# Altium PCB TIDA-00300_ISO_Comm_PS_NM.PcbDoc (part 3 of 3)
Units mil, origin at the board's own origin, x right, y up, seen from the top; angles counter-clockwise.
Board outline 2559.06 x 6299.21 mil, 4 copper layers (Top Layer, GND Layer, PWR Layer, Bottom Layer), stack 61.6 mil thick; 303 components, 144 nets, 678 pads, 244 vias.
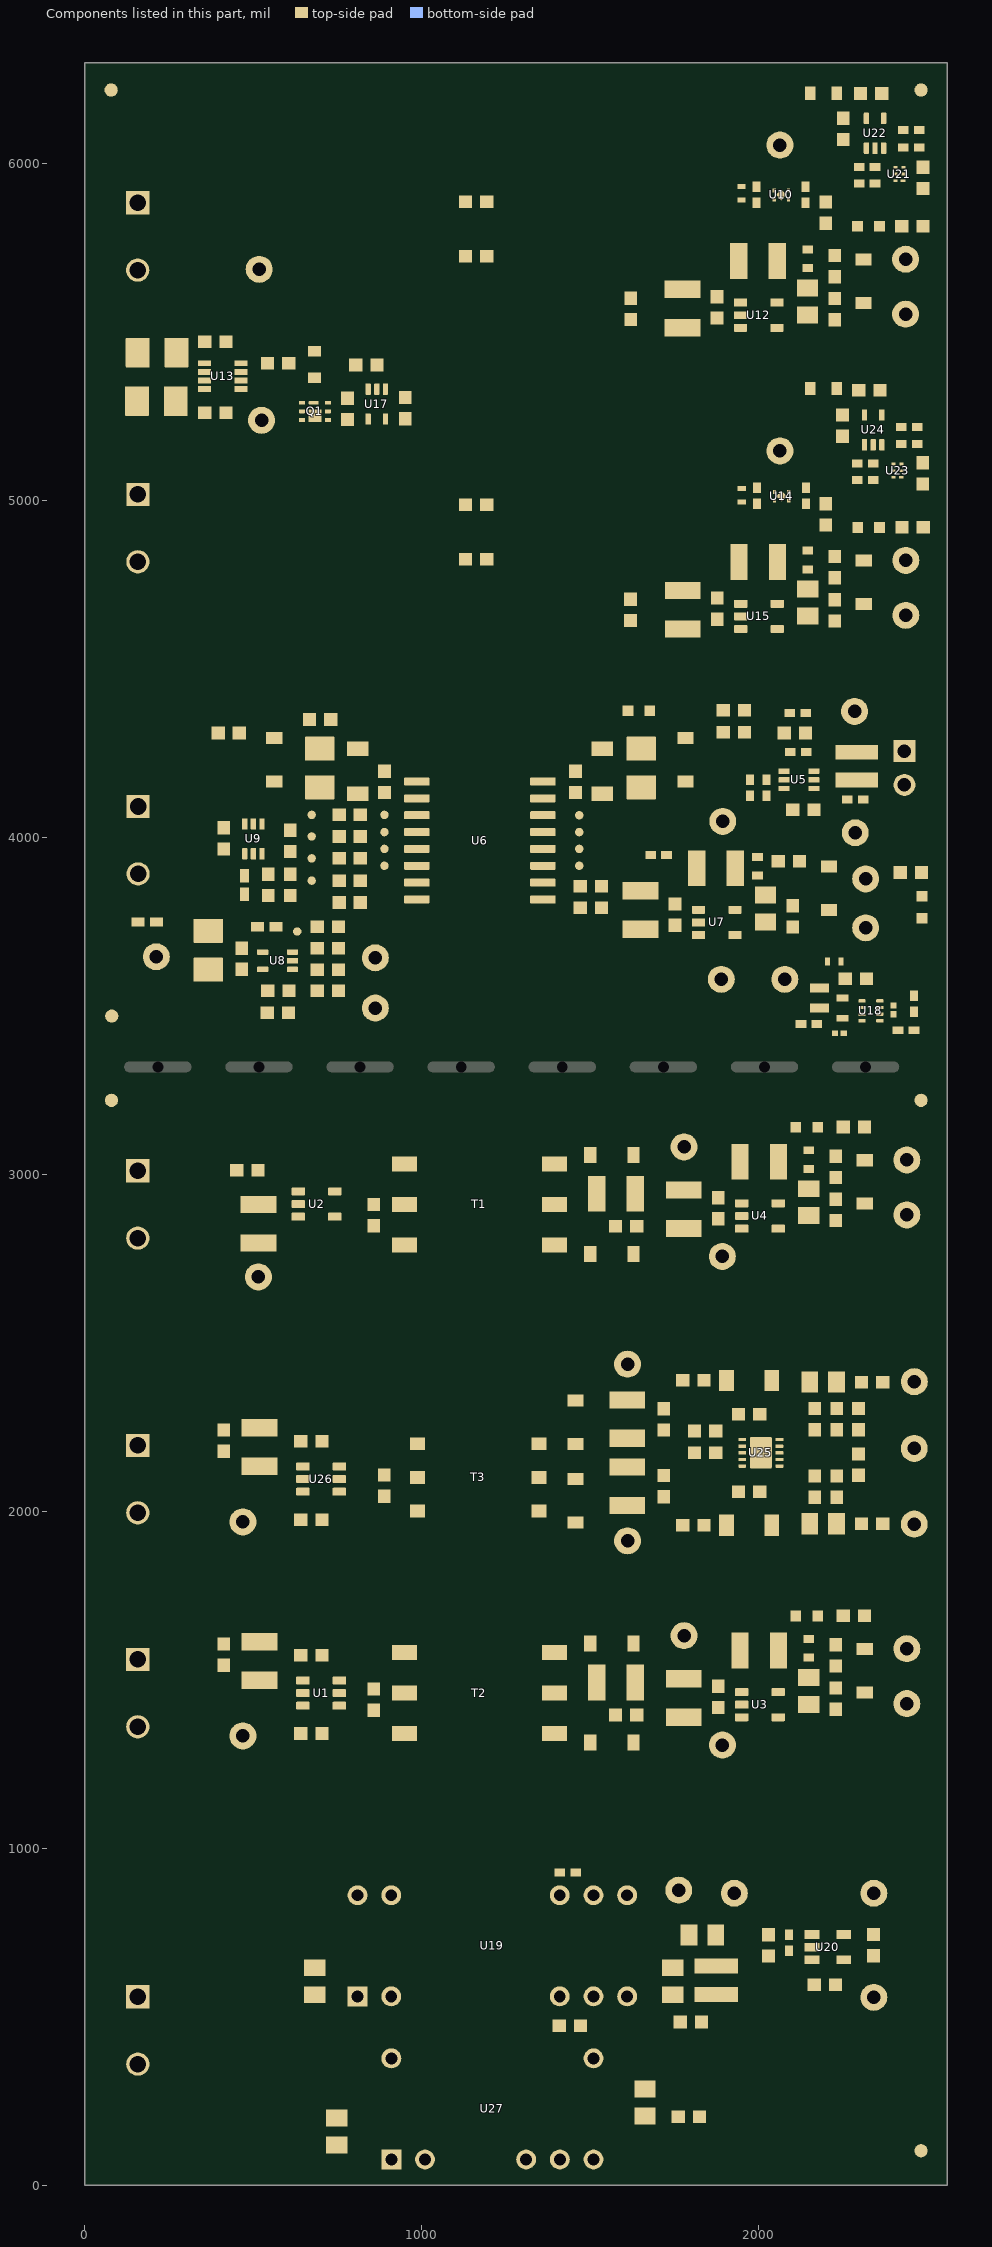
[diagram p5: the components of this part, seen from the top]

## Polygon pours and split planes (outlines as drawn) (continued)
NetC64_2 on Top Layer "vdd" (solid, remove dead copper, pour order 238): 1962.14,4669.8 1560.87,4669.8 1550.07,4659 1550.07,4561.8 1562.07,4549.8 1895.34,4549.8 1903.34,4557.8 1903.34,4634.58 1911.07,4642.31 1963.5,4642.31 1968.55,4647.36 1968.55,4663.11
IGND_5 on Top Layer "vdd" (solid, remove dead copper, pour order 236): 1860.07,4871.8 1852.07,4863.8 1852.07,4775.8 1845.07,4768.8 1670.07,4768.8 1661.07,4759.8 1661.07,4693.8 1665.07,4689.8 1915.07,4689.8 1922.07,4682.8 1964.55,4682.8 1968.55,4686.8 1968.55,4869.33 1966.07,4871.8
NetC68_2 on Top Layer "vdd" (solid, remove dead copper, pour order 234): 2165.07,4879.8 2168.07,4876.8 2168.07,4839.8 2163.07,4834.8 2100.07,4834.8 2089.07,4823.8 2089.07,4767.8 2082.07,4760.8 2042.07,4760.8 2027.07,4775.8 2027.07,4874.73 2032.14,4879.8
NetC66_2 on Top Layer "vdd" (solid, remove dead copper, pour order 232): 2163.79,4809.09 2111.79,4809.09 2107.79,4805.09 2107.79,4711.09 2110.79,4708.09 2193.79,4708.09 2201.79,4700.09 2201.79,4688.09 2205.79,4684.09 2248.79,4684.09 2251.79,4687.09 2251.79,4786.09 2248.79,4789.09 2183.79,4789.09
IGND_5 on Top Layer "vdd" (solid, remove dead copper, pour order 228): 2479.79,4723.09 2494.79,4708.09 2494.79,4574.09 2473.79,4553.09 2115.79,4553.09 2104.79,4564.09 2104.79,4680.09 2110.79,4686.09 2175.79,4686.09 2198.78,4663.11 2269.01,4663.11 2274.79,4668.89 2274.79,4716.09 2281.79,4723.09
IGND_4 on Top Layer "vdd" (solid, remove dead copper, pour order 226): 2479.14,5616.78 2494.14,5601.78 2494.14,5467.78 2480.21,5453.85 2108.07,5453.85 2104.14,5457.78 2104.14,5573.78 2110.14,5579.78 2175.14,5579.78 2198.12,5556.8 2268.36,5556.8 2274.14,5562.58 2274.14,5609.78 2281.14,5616.78
+5.0V_3.3V_VDC_4 on Top Layer "vdd" (solid, remove dead copper, pour order 224): 27 vertices, not listed, extent 2169.46,5675.49 2517.93,5955.85
NetC49_2 on Top Layer "vdd" (solid, remove dead copper, pour order 222): 2163.14,5702.78 2111.14,5702.78 2107.14,5698.78 2107.14,5604.78 2110.14,5601.78 2193.14,5601.78 2201.14,5593.78 2201.14,5581.78 2205.14,5577.78 2248.14,5577.78 2251.14,5580.78 2251.14,5679.78 2248.14,5682.78 2183.14,5682.78
NetC51_2 on Top Layer "vdd" (solid, remove dead copper, pour order 220): 2164.42,5773.49 2167.42,5770.49 2167.42,5733.49 2162.42,5728.49 2099.42,5728.49 2088.42,5717.49 2088.42,5661.49 2081.42,5654.49 2041.42,5654.49 2026.42,5669.49 2026.42,5768.42 2031.49,5773.49
IGND_4 on Top Layer "vdd" (solid, remove dead copper, pour order 218): 1859.42,5765.49 1851.42,5757.49 1851.42,5669.49 1844.42,5662.49 1669.42,5662.49 1660.42,5653.49 1660.42,5587.49 1664.42,5583.49 1914.42,5583.49 1921.42,5576.49 1963.89,5576.49 1967.89,5580.49 1967.89,5763.02 1965.42,5765.49
NetC47_2 on Top Layer "vdd" (solid, remove dead copper, pour order 216): 1961.49,5563.49 1560.22,5563.49 1549.42,5552.69 1549.42,5466.09 1561.65,5453.85 1897,5453.85 1902.69,5459.54 1902.69,5528.27 1910.42,5536 1962.84,5536 1967.89,5541.05 1967.89,5556.8
NetC56_1 on Top Layer "vdd" (solid, remove dead copper, pour order 214): 1942.58,5019.29 1929.16,5032.72 1929.16,5058.89 1934.07,5063.8 2010.07,5063.8 2014.07,5059.8 2014.07,5022.29 2011.07,5019.29
DVDD_I_5 on Top Layer "vdd" (solid, remove dead copper, pour order 212): 1873.02,5008.8 1862.45,4998.24 1862.45,4896.41 1866.06,4892.8 1952.07,4892.8 1962.07,4902.8 1962.07,5006.8 1960.07,5008.8
NetC39_1 on Top Layer "vdd" (solid, remove dead copper, pour order 206): 1941.93,5912.98 1928.5,5926.41 1928.5,5952.58 1933.42,5957.49 2009.42,5957.49 2013.42,5953.49 2013.42,5915.98 2010.42,5912.98
DVDD_I_4 on Top Layer "vdd" (solid, remove dead copper, pour order 200): 1861.42,5902.49 1856.42,5897.49 1856.42,5791.49 1861.42,5786.49 1951.42,5786.49 1961.42,5796.49 1961.42,5900.49 1959.42,5902.49
NetD22_1 on Top Layer "vdd" (solid, remove dead copper, pour order 192): 623,5271.8 619,5267.8 619,5208.87 622.07,5205.8 730.02,5205.8 735,5210.78 735,5268.8 732,5271.8
GND_4 on Top Layer "vdd" (solid, remove dead copper, pour order 180): 199,5252.54 182,5235.54 80.73,5235.54 68,5248.28 68,5487.65 78,5497.65 194.15,5497.65 199,5492.8
no net on Top Layer "vdd" (solid, remove dead copper, pour order 178): 158,5457.8
VCC_LS_5 on Top Layer "vdd" (solid, remove dead copper, pour order 176): 550.89,4933 455,5028.89 455,5300.8 439,5316.8 439,5338.8 441,5340.8 561,5340.8 566,5335.8 566,5141 664,5043 1141.34,5043 1150.72,5033.62 1150.72,4939.72 1144,4933
DVDD_5 on Top Layer "vdd" (solid, remove dead copper, pour order 174): 119,4979.85 123,4975.85 189,4975.85 378,5164.85 378,5361.8 376,5363.8 250,5363.8 233,5346.8 233,5230.8 119,5116.8
DVDD_4 on Top Layer "vdd" (solid, remove dead copper, pour order 172): 351.98,5601.87 228,5725.85 125,5725.85 117,5717.85 117,5552.8 127,5542.8 208,5542.8 234,5516.8 234,5390.8 241,5383.8 319,5383.8 332,5370.8 372,5370.8 376,5374.8 376,5577.85
VCC_LS_4 on Top Layer "vdd" (solid, remove dead copper, pour order 170): 18 vertices, not listed, extent 441,5374.8 1150.46,5792
GND_2 on Top Layer "vdd" (solid, remove dead copper, pour order 164): 125.64,2849.8 578.89,2849.8 613.74,2814.94 613.74,2671.8 595.74,2653.8 117.74,2653.8 117.74,2841.9
NetC1_2 on Top Layer "vdd" (solid, remove dead copper, pour order 162): 486.74,2975.8 454.74,2943.8 454.74,2886.8 459.74,2881.8 573.74,2881.8 585.74,2893.8 585.74,3052.8 578.74,3059.8 493.6,3059.8 486.74,3052.94
IGND_3 on Top Layer "vdd" (solid, remove dead copper, pour order 140): 2319.66,3509.85 2324.71,3514.91 2324.71,3539.01 2328.77,3543.06 2372.98,3543.06 2377.77,3547.85 2377.77,3605.85 2371.77,3611.85 2302.58,3611.85 2297.58,3606.85 2297.58,3552.89 2281.37,3536.68 2228.66,3536.68 2228.66,3509.85
NetC70_1 on Top Layer "vdd" (solid, remove dead copper, pour order 138): 2228.92,3647.85 2228.66,3604.74 2218.77,3594.85 2125.77,3594.85 2100.77,3619.85 2019.77,3619.85 2011.53,3611.62 2011.53,3546.08 2020.77,3536.85 2202.77,3536.85 2224.77,3558.85 2271.77,3558.85 2275.77,3562.85 2275.77,3645.07 2272.98,3647.85
NetC35_2 on Top Layer "vdd" (solid, remove dead copper, pour order 136): 2004.08,3972.05 2012.77,3963.37 2012.77,3929.55 2009.27,3926.05 1965.49,3926.05 1957.49,3918.05 1957.49,3772.05 1954.49,3769.05 1906.24,3769.05 1901.49,3773.8 1901.49,3965.05 1908.49,3972.05
+5.0V_VDC_3 on Top Layer "vdd" (solid, remove dead copper, pour order 134): 19 vertices, not listed, extent 1982.77,3776.85 2362.77,3951.85
IGND_3 on Top Layer "vdd" (solid, remove dead copper, pour order 130): 2370.49,3787.13 2370.49,3680.57 2361.77,3671.85 1988.77,3671.85 1980.49,3680.13 1980.49,3773.05 1986.49,3779.05 2051.49,3779.05 2074.47,3756.07 2171.98,3756.07 2177.82,3761.91 2177.82,3795.91 2182.97,3801.05 2356.57,3801.05
NetC31_2 on Top Layer "vdd" (solid, remove dead copper, pour order 128): 1700.49,3967.1 1695.54,3972.05 1590.97,3972.05 1581.77,3962.85 1581.77,3791.35 1590.77,3782.35 1791.19,3782.35 1798.49,3775.05 1842.49,3775.05 1842.49,3824.05 1837.49,3829.05 1734.49,3829.05 1700.49,3863.05
IGND_3 on Top Layer "vdd" (solid, remove dead copper, pour order 124): 17 vertices, not listed, extent 1574.49,3592.05 1843.24,3763.05
DVDD_I_5.4V_3 on Top Layer "vdd" (solid, remove dead copper, pour order 114): 2141.8,4149.67 2141.8,3991.82 2160.77,3972.85 2335.84,3972.85 2351.84,3988.85 2351.84,4064.8 2343.79,4072.85 2217.77,4072.85 2192.77,4097.85 2192.77,4145.37 2184.29,4153.85 2145.98,4153.85
NetC25_1 on Top Layer "vdd" (solid, remove dead copper, pour order 108): 2124.77,4232.85 2134.77,4222.85 2470.77,4222.85 2482.77,4234.85 2482.77,4318.85 2473.77,4327.85 2189.77,4327.85 2175.77,4341.85 2175.77,4389.35 2171.77,4393.35 2128.27,4393.35 2124.77,4389.85
no net on Top Layer "vdd" (solid, remove dead copper, pour order 106): 2128.31,4354.85
IGND_3 on Top Layer "vdd" (solid, remove dead copper, pour order 104): 1543.77,4192.85 1504.77,4153.85 1434.51,4153.85 1412.77,4132.11 1325.03,4132.11 1319.77,4126.85 1319.77,4098.39 1322.77,4095.39 1492.22,4095.39 1540.77,4046.85 1827.77,4046.85 1840.27,4059.35 1840.27,4186.35 1833.77,4192.85
DVDD_I_3 on Top Layer "vdd" (solid, remove dead copper, pour order 102): 2097.77,4414.85 1943.68,4414.85 1937.77,4408.94 1937.77,4231.87 1943.77,4225.87 2008.79,4225.87 2012.79,4229.87 2012.79,4338.87 2027.77,4353.85 2098.77,4353.85 2101.77,4356.85 2101.77,4410.85
ISO_VOUT on Top Layer "vdd" (solid, remove dead copper, pour order 100): 17 vertices, not listed, extent 1319.77,4149.85 1916.77,4365.85
GND_3 on Top Layer "vdd" (solid, remove dead copper, pour order 96): 17 vertices, not listed, extent 60.77,4052.85 1024.77,4192.85
NetC20_2 on Top Layer "vdd" (solid, remove dead copper, pour order 94): 18 vertices, not listed, extent 435.77,4152.11 1024.77,4412.85
no net on Top Layer "vdd" (solid, remove dead copper, pour order 92): 896.77,4297.85
GND_3 on Top Layer "vdd" (solid, remove dead copper, pour order 88): 447.77,3653.85 420.77,3680.85 320.85,3680.85 306.71,3694.99 306.71,3791.8 320.77,3805.85 433.81,3805.85 440.31,3799.35 440.31,3749.71 492.83,3697.19 492.83,3655.92 490.77,3653.85
NetR25_2 on Top Layer "vdd" (solid, remove dead copper, pour order 84): 639.77,3617.85 659.77,3637.85 704.77,3637.85 709.77,3632.85 709.77,3583.31 705.77,3579.31 598.31,3579.31 593.77,3583.85 593.77,3616.85 594.77,3617.85
VCC_LS_3 on Top Layer "vdd" (solid, remove dead copper, pour order 82): 729.77,3585.85 734.77,3580.85 914.77,3580.85 922.77,3588.85 922.77,3749.47 909.38,3762.85 732.77,3762.85 729.77,3759.85
no net on Top Layer "vdd" (solid, remove dead copper, pour order 80): 756.77,3741.85
NetJ4_2 on Top Layer "vdd" (solid, remove dead copper, pour order 76): 195.77,3862.85 178.77,3845.85 178.77,3719.85 172.77,3713.85 65.77,3713.85 57.77,3721.85 57.77,3920.87 66.77,3929.87 193.75,3929.87 195.77,3927.85
DVDD_3 on Top Layer "vdd" (solid, remove dead copper, pour order 74): 19 vertices, not listed, extent 158.77,3516.31 563.77,3779.58
+5V_2 on Top Layer "vdd" (solid, remove dead copper, pour order 64): 224.74,2970.94 118.74,2970.94 110.74,2978.94 110.74,3070.94 122.74,3082.94 457.6,3082.94 472.43,3068.12 472.43,2986.69 456.68,2970.94
GND_VDC_2 on Top Layer "vdd" (solid, remove dead copper, pour order 60): 21 vertices, not listed, extent 1353.74,2813.94 1590.01,2999.94
NetD1_2 on Top Layer "vdd" (solid, remove dead copper, pour order 58): 1361.74,3087.94 1353.74,3079.94 1353.74,3011.94 1358.74,3006.94 1432.74,3006.94 1458.74,3032.94 1519.74,3032.94 1523.74,3036.94 1523.74,3084.94 1520.74,3087.94
NetD3_2 on Top Layer "vdd" (solid, remove dead copper, pour order 56): 1361.74,2733.94 1353.74,2741.94 1353.74,2809.94 1358.74,2814.94 1432.74,2814.94 1458.74,2788.94 1519.74,2788.94 1523.74,2784.94 1523.74,2736.94 1520.74,2733.94
no net on Top Layer "vdd" (solid, remove dead copper, pour order 54): 1892.74,2908.94
no net on Top Layer "vdd" (solid, remove dead copper, pour order 52): 1932.74,2899.94
+6V_VDC_2 on Top Layer "vdd" (solid, remove dead copper, pour order 50): 22 vertices, not listed, extent 1605.74,2719.94 1970.74,3139.94
NetC19_2 on Top Layer "vdd" (solid, remove dead copper, pour order 48): 2029.74,2902.7 2034.49,2897.94 2082.74,2897.94 2085.74,2900.94 2085.74,3046.94 2093.74,3054.94 2172.74,3054.94 2175.74,3057.94 2175.74,3096.94 2171.74,3100.94 2036.74,3100.94 2029.74,3093.94
NetC15_2 on Top Layer "vdd" (solid, remove dead copper, pour order 46): 2166.74,3029.94 2114.74,3029.94 2110.74,3025.94 2110.74,2931.94 2113.74,2928.94 2196.74,2928.94 2204.74,2920.94 2204.74,2908.94 2208.74,2904.94 2251.74,2904.94 2254.74,2907.94 2254.74,3006.94 2251.74,3009.94 2186.74,3009.94
+5.0V_VDC_2 on Top Layer "vdd" (solid, remove dead copper, pour order 44): 19 vertices, not listed, extent 2201.74,2988.94 2496.74,3180.86
GND_VDC_2 on Top Layer "vdd" (solid, remove dead copper, pour order 42): 2482.74,2943.94 2497.74,2928.94 2497.74,2794.94 2476.74,2773.94 2118.74,2773.94 2107.74,2784.94 2107.74,2900.94 2113.74,2906.94 2178.74,2906.94 2201.73,2883.96 2271.96,2883.96 2277.74,2889.75 2277.74,2936.94 2284.74,2943.94
GND_VDC_2 on Top Layer "vdd" (solid, remove dead copper, pour order 40): 17 vertices, not listed, extent 1702.74,2720.94 1971.49,2891.94
GND_VDC_1 on Top Layer "vdd" (solid, remove dead copper, pour order 26): 17 vertices, not listed, extent 1702.74,1270.85 1971.49,1441.85
GND_VDC_1 on Top Layer "vdd" (solid, remove dead copper, pour order 24): 2482.74,1493.85 2497.74,1478.85 2497.74,1344.85 2476.74,1323.85 2118.74,1323.85 2107.74,1334.85 2107.74,1450.85 2113.74,1456.85 2178.74,1456.85 2201.73,1433.87 2271.96,1433.87 2277.74,1439.65 2277.74,1486.85 2284.74,1493.85
+3.3V_VDC_1 on Top Layer "vdd" (solid, remove dead copper, pour order 22): 2270.74,1581.85 2313.74,1538.85 2485.74,1538.85 2496.74,1549.85 2496.74,1721.76 2487.74,1730.76 2298.66,1730.76 2290.74,1722.85 2290.74,1649.85 2285.74,1644.85 2205.74,1644.85 2201.74,1640.85 2201.74,1585.85 2205.74,1581.85
NetC14_2 on Top Layer "vdd" (solid, remove dead copper, pour order 20): 2166.74,1579.85 2114.74,1579.85 2110.74,1575.85 2110.74,1481.85 2113.74,1478.85 2196.74,1478.85 2204.74,1470.85 2204.74,1458.85 2208.74,1454.85 2251.74,1454.85 2254.74,1457.85 2254.74,1556.85 2251.74,1559.85 2186.74,1559.85
NetC18_2 on Top Layer "vdd" (solid, remove dead copper, pour order 18): 2029.74,1452.6 2034.49,1447.85 2082.74,1447.85 2085.74,1450.85 2085.74,1596.85 2093.74,1604.85 2172.74,1604.85 2175.74,1607.85 2175.74,1646.85 2171.74,1650.85 2036.74,1650.85 2029.74,1643.85
+6V_VDC_1 on Top Layer "vdd" (solid, remove dead copper, pour order 16): 22 vertices, not listed, extent 1605.74,1269.85 1970.74,1689.85
no net on Top Layer "vdd" (solid, remove dead copper, pour order 14): 1932.74,1449.85
no net on Top Layer "vdd" (solid, remove dead copper, pour order 12): 1892.74,1458.85
NetD4_2 on Top Layer "vdd" (solid, remove dead copper, pour order 10): 1361.74,1283.85 1353.74,1291.85 1353.74,1359.85 1358.74,1364.85 1432.74,1364.85 1458.74,1338.85 1519.74,1338.85 1523.74,1334.85 1523.74,1286.85 1520.74,1283.85
NetD2_2 on Top Layer "vdd" (solid, remove dead copper, pour order 8): 1361.74,1637.85 1353.74,1629.85 1353.74,1561.85 1358.74,1556.85 1432.74,1556.85 1458.74,1582.85 1519.74,1582.85 1523.74,1586.85 1523.74,1634.85 1520.74,1637.85
GND_VDC_1 on Top Layer "vdd" (solid, remove dead copper, pour order 6): 21 vertices, not listed, extent 1353.74,1363.85 1590.01,1549.85
GND_1 on Top Layer "vdd" (solid, remove dead copper, pour order 4): 23 vertices, not listed, extent 110.74,1260.85 669.27,1596.87
+5V_1 on Top Layer "vdd" (solid, remove dead copper, pour order 2): 262.2,1563.39 224.74,1600.85 118.74,1600.85 110.74,1592.85 110.74,1500.85 122.74,1488.85 433.74,1488.85 438.74,1493.85 438.74,1557.45 432.8,1563.39
NetC2_2 on Top Layer "vdd" (solid, remove dead copper, pour order 0): 17 vertices, not listed, extent 378.2,1545.65 739.74,1711.85
GND_BI on Bottom Layer "vdd" (solid, remove dead copper, pour order 350): 2499,2493.85 2518.74,2474.11 2518.74,1908.25 2476.34,1865.85 1342,1865.85 1325,1882.85 1325,2482.43 1336.42,2493.85
no net on Bottom Layer "vdd" (solid, remove dead copper, pour order 348): 1003,2492.85
GND_B on Bottom Layer "vdd" (solid, remove dead copper, pour order 346): 986,2493.85 79,2493.85 55.74,2470.59 55.74,1886.11 76,1865.85 985,1865.85 1007.74,1888.59 1007.74,2472.11
no net on Bottom Layer "vdd" (solid, remove dead copper, pour order 326): 1000.74,2273.85
no net on Bottom Layer "vdd" (solid, remove dead copper, pour order 324): 996.32,2231.87
+5.0V_VDC_3 on Bottom Layer "vdd" (solid, remove dead copper, pour order 288): 2076.77,3820.26 2099.77,3797.26 2099.77,3646.59 2136.51,3609.85 2198,3609.85 2200,3611.85 2200,3873.36 2160.51,3912.85 2105.77,3912.85 2076.77,3883.85
GND_6 on Bottom Layer "vdd" (solid, remove dead copper, pour order 282): 1009,437 1044.08,401.92 1044.08,53.08 1022,31 95,31 57.33,68.67 57.33,925.33 76,944 1001,944 1009,936
GND_VDC_6 on Bottom Layer "vdd" (solid, remove dead copper, pour order 280): 1324,451 1274,401 1274,58 1289,43 2470,43 2518.74,91.74 2518.74,934.26 2509,944 1344,944 1324,924
no net on Bottom Layer "vdd" (solid, remove dead copper, pour order 144): 2128.31,3840.85
DVDD_I_5.4V_3 on Bottom Layer "vdd" (solid, remove dead copper, pour order 116): 1854.77,3934.85 1773.77,3853.85 1702.77,3853.85 1680.77,3875.85 1680.77,4127.85 1703.77,4150.85 2187.29,4150.85 2192.77,4145.37 2192.77,4097.85 2217.77,4072.85 2343.79,4072.85 2351.84,4064.8 2351.84,3947.92 2338.77,3934.85
NetC25_1 on Bottom Layer "vdd" (solid, remove dead copper, pour order 110): 2076.77,4295.85 2025.77,4244.85 2025.77,4207.85 2032.77,4200.85 2147.8,4200.85 2171.8,4224.85 2203.77,4224.85 2208.77,4229.85 2208.77,4293.85 2206.77,4295.85
no net on Bottom Layer "vdd" (solid, remove dead copper, pour order 86): 474.77,3639.85
NetJ4_2 on Bottom Layer "vdd" (solid, remove dead copper, pour order 78): 195.77,3862.85 178.77,3845.85 178.77,3719.85 172.77,3713.85 65.77,3713.85 57.77,3721.85 57.77,3920.87 66.77,3929.87 193.75,3929.87 195.77,3927.85
GND_2 on Bottom Layer "vdd" (solid, remove dead copper, pour order 70): 1007.74,3190.8 990.74,3207.8 69.74,3207.8 55.74,3193.8 55.74,2658.94 89.74,2624.94 999.74,2624.94 1007.74,2632.94
GND_VDC_2 on Bottom Layer "vdd" (solid, remove dead copper, pour order 62): 2503.74,3209.8 1358.74,3209.8 1323.74,3174.8 1323.74,2641.94 1340.74,2624.94 2490.74,2624.94 2518.74,2652.94 2518.74,3194.8
GND_1 on Bottom Layer "vdd" (solid, remove dead copper, pour order 38): 1007.74,1717.76 994.74,1730.76 72.91,1730.76 55.74,1713.59 55.74,1251.11 76,1230.85 985,1230.85 1007.74,1253.59
no net on Bottom Layer "vdd" (solid, remove dead copper, pour order 36): 1007.74,1612.94
no net on Bottom Layer "vdd" (solid, remove dead copper, pour order 34): 996.32,1596.87
no net on Bottom Layer "vdd" (solid, remove dead copper, pour order 32): 1000.74,1638.85
GND_VDC_1 on Bottom Layer "vdd" (solid, remove dead copper, pour order 28): 2487.74,1730.76 1348.66,1730.76 1323.74,1705.85 1323.74,1252.11 1344,1231.85 2502,1231.85 2518.74,1248.59 2518.74,1724.85 2512.74,1730.85
IGND_4 on GND Layer "vdd" (solid, remove dead copper, pour order 254): 1171.41,5464.59 1171.41,6228.41 1187.85,6244.85 2478,6244.85 2517.93,6204.92 2517.93,5476.85 2494.93,5453.85 1182.15,5453.85
IGND_5 on GND Layer "vdd" (solid, remove dead copper, pour order 248): 1189.57,5427.57 2496.28,5427.57 2519,5404.85 2519,4516.8 2499,4496.8 1187.01,4496.8 1171.48,4512.33 1171.41,5409.41
GND_4 on GND Layer "vdd" (solid, remove dead copper, pour order 240): 56.42,4517.39 77,4496.8 1135.8,4496.8 1150.72,4511.72 1150.34,6216.66 1122.14,6244.85 79,6244.85 56.42,6222.27
GND_3 on GND Layer "vdd" (solid, remove dead copper, pour order 152): 84.77,4416.85 56.77,4388.85 56.77,3429.85 83.77,3402.85 1005.85,3402.85 1024,3421 1024,4403 1010.15,4416.85
IGND_3 on GND Layer "vdd" (solid, remove dead copper, pour order 150): 1076,3420.26 1076,4407 1085.85,4416.85 2492.77,4416.85 2519.77,4389.85 2519.77,3409.85 2512.77,3402.85 1093.41,3402.85
DVDD_I_4 on PWR Layer "vdd" (solid, remove dead copper, pour order 342): 1171.43,5453.85 1171.43,6228.43 1187.85,6244.85 2478,6244.85 2517.93,6204.92 2517.93,5476.85 2494.93,5453.85
DVDD_I_5 on PWR Layer "vdd" (solid, remove dead copper, pour order 252): 1189.57,5427.57 2496.28,5427.57 2519,5404.85 2519,4516.8 2499,4496.8 1187.01,4496.8 1171.51,4512.31 1171.43,5409.43
DVDD_4 on PWR Layer "vdd" (solid, remove dead copper, pour order 246): 1122.14,6244.85 79,6244.85 56.42,6222.27 56.42,5466.49 65.42,5457.49 968.5,5457.49 1134.5,5457.49 1150.54,5473.55 1150.23,6216.77
DVDD_5 on PWR Layer "vdd" (solid, remove dead copper, pour order 242): 57,5406.43 57,4516.8 77,4496.8 1135.8,4496.8 1150.77,4511.77 1150.77,5412.23 1133.15,5429.85 80.42,5429.85
VCC_LS_3 on PWR Layer "vdd" (solid, remove dead copper, pour order 160): 780.77,3402.85 1261.85,3402.85 1273,3414 1273,4396 1252.15,4416.85 711.77,4416.85 697.77,4402.85 697.77,4361.85 780.77,4278.85
DVDD_3 on PWR Layer "vdd" (solid, remove dead copper, pour order 158): 757.77,3417.85 742.77,3402.85 83.77,3402.85 56.77,3429.85 56.77,4388.85 84.77,4416.85 610.77,4416.85 757.77,4269.85
DVDD_I_3 on PWR Layer "vdd" (solid, remove dead copper, pour order 154): 1345.77,3402.85 1324.77,3423.85 1324.77,3785.85 1324.77,4201.85 1324.77,4384.85 1354.77,4414.85 2494.77,4414.85 2519.77,4389.85 2519.77,3409.85 2512.77,3402.85

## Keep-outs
Keep-Out Layer:
  the board outline again, w10
  text ".Layer_Name" at 234.72,-1266.73 h60

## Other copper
Top Layer:
  region net +5.0V_3.3V_VDC_5: 2222.31,5108.93
  region net +5.0V_3.3V_VDC_4: 2227.79,5989.06
  text ".Layer_Name" at 234.72,-1266.73 h60
GND Layer:
  text ".Layer_Name" at 233,-1268.15 h60
PWR Layer:
  text ".Layer_Name" at 229,-1268.15 h60
Bottom Layer:
  text ".Layer_Name" at 234.72,-1266.73 h60

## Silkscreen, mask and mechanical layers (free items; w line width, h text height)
Top Overlay:
  lines w6: 433.77,3855.45 438.37,3850.85 438.37,3861.45 433.77,3856.85 448.47,3856.85 ; 488.02,3498.16 507.44,3517.58 513.78,3517.58 ; 755.82,4295.85 802.77,4342.8 802.77,4372.85 ; 780.75,3580.58 797.31,3580.58 809.22,3568.68 820.77,3568.68 ; 780.75,3698.75 809.67,3698.75 820.47,3709.55 918.77,3709.55 ; 780.75,3762.05 893.07,3762.05 912.27,3742.85 924.77,3742.85 ; 2016.13,4216.85 2021.77,4211.21 2021.77,4210.84 2021.77,4208.7 2021.77,4196.85 ; 2064.34,3461.78 2070.68,3468.12 2099.08,3468.12 ; 2132.51,4023.85 2132.51,4049.85 ; 2151.6,5838.04 2166.07,5838.04 ; 2153.17,5095.85 2160.72,5088.29 2160.72,5063 ; 2155,5987.49 2160.07,5982.42 2160.07,5956.69 ; 2156.22,4940.07 2165,4940.07 ; 2164.77,4258.85 2196.77,4258.85 2208.77,4270.85 2208.77,4281.85 ; 2194,3400.06 2204.55,3410.6 2204.55,3442.02 2212.59,3450.07 2228.66,3450.07 ; 2210,3084.85 2210,3180.85 ; 2252.27,4861.79 2252.27,4877.84 ; 2265.56,4939.85 2265.56,4949.85 ; 2495.58,5240 2495.58,5279.85 2489,5273.27 2503,5273.27 2496.42,5279.85 ; 2501.05,6025.83 2513.74,6025.83
  lines w20: 0,1077.85 2558,1077.85 ; 0,1799.85 2558,1799.85 ; 0,2533.85 2558,2533.85 ; 0,3318.94 2558,3318.94 ; 0.77,4458.85 2558.77,4458.85
  text ".PRJ_Number" at 581.97,6173.8 h50
  text "-E2" at 1824.79,6172 h50
  text ".Layer_Name" at 234.72,-1266.73 h60
Bottom Overlay:
  text ".Layer_Name" at 234.72,-1266.73 h60
Top Paste:
  text ".Layer_Name" at 234.72,-1266.73 h60
Bottom Paste:
  text ".Layer_Name" at 234.72,-1266.73 h60
Top Solder:
  text ".Layer_Name" at 234.72,-1266.73 h60
  text ".Layer_Name" at 234.72,-1266.73 h60
Bottom Solder:
  text ".Layer_Name" at 234.72,-1266.73 h60
Drill Guide:
  text ".Layer_Name" at 234.72,-1266.73 h60
M1 Board Outline:
  the board outline again, w10
M2 Board Dimensions:
  rectangle: -217.28,-808.24 157.72,-683.24
  rectangle: -342.28,-683.24 -217.28,-558.24
  lines w7: -342.28,-683.24 657.72,-683.24 ; -217.28,-808.24 -217.28,-558.24 ; -92.28,-808.24 -92.28,-558.24 ; 157.72,-808.24 157.72,-558.24 ; 407.72,-808.24 407.72,-558.24 ; -342.28,-808.24 -342.28,-558.24 657.72,-558.24 657.72,-808.24 -342.28,-808.24
M3 3D STEP Top:
  text ".Layer_Name" at 234.72,-1266.73 h60
M4 3D STEP Bottom:
  text ".Layer_Name" at 234.72,-1266.73 h60
M5 Assembly Top:
  circle w6: c2319,6031.85 r6.82
  circle w6: c2314,5151.85 r6.82
  circle w6: c2428.77,4253.85 r10.3
  lines w10: -634.28,-1338.4 5965.72,-1338.4 ; -634.28,-1135.07 5967.72,-1135.07 ; -634.28,-931.74 -634.28,-1541.74 3370.72,-1541.74 5967.72,-1541.74 5967.72,-931.74 -633.78,-931.74 -633.78,-1541.74 941.72,-1541.74 ; 1830.72,-1541.74 1830.72,-931.74 ; 3097.72,-1135.07 3097.72,-931.74 ; 3937.72,-1135.07 3937.72,-931.74 ; 4559.72,-1548.24 4559.72,-1345.4
  text "COMPONENTS MARKED 'DNP' SHOULD NOT BE POPULATED." at 811.22,-726.74 h20
  text "ASSEMBLY VARIANT:" at 810.72,-842.24 h20
  text ".VariantName" at 1846.72,-842.24 h20
  text "PCB VIEWED FROM TOP SIDE" at -570.78,-1063.9 h20
  text "BOARD #:" at 1905.72,-1063.9 h20
  text ".PRJ_Number" at 2451.22,-1063.9 h20
  text "REV:" at 3295.72,-1063.9 h20
  text ".PCB_Rev" at 3587.22,-1063.9 h20
  text "SVN REV:" at 4133.72,-1063.9 h20
  text ".VersionControl_RevNumber" at 4639.72,-1063.9 h20
  text ".Layer_Name" at 227,-1266.15 h20
  text "TID #:" at 1905.72,-1267.24 h20
  text ".TID" at 2451.22,-1267.24 h20
  text "LAYER NAME =" at -570.78,-1268.73 h20
  text "PLOT NAME =" at -570.78,-1472.57 h20
  text ".plot_File_Name" at 234.72,-1472.57 h20
  text "GENERATED    :" at 1907.72,-1472.57 h20
  text ".Print_Date" at 2777.22,-1472.57 h20
  text ".Print_Time" at 3506.22,-1472.57 h20
  text "TEXAS INSTRUMENTS" at 4770.72,-1472.57 h20
M6 Assembly Bottom:
  lines w10: -634.78,-1135.57 5967.22,-1135.57 ; -632.78,-1338.9 5967.22,-1338.9 ; 773.22,-1548.74 773.22,-1345.9 ; 1395.22,-1135.57 1395.22,-932.24 ; 1932,-1131.48 1932,-928.15 ; 3502.22,-1542.24 3502.22,-932.24 ; 4391.22,-1542.24 5966.72,-1542.24 5966.72,-932.24 -634.78,-932.24 -634.78,-1542.24 1962.22,-1542.24 5967.22,-1542.24 5967.22,-932.24
  text "COMPONENTS MARKED 'DNP' SHOULD NOT BE POPULATED." at 5759.72,-726.24 h60
  text ".VariantName" at 4715.72,-842.24 h60
  text "ASSEMBLY VARIANT:" at 5754.72,-842.24 h60
  text "REV:" at 1786,-1061.15 h60
  text ".VersionControl_RevNumber" at 693.22,-1064.4 h60
  text "SVN REV:" at 1199.22,-1064.4 h60
  text "BOARD #:" at 3427.22,-1064.4 h40
  text "PCB VIEWED FROM BOTTOM SIDE" at 5903.72,-1064.4 h60
  text ".PCB_Rev" at 1537,-1065.15 h60
  text ".PRJ_Number" at 3135,-1076.15 h40
  text ".TID" at 2881.72,-1267.74 h60
  text "TID #:" at 3427.22,-1267.74 h60
  text "TEXAS INSTRUMENTS" at 562.22,-1473.07 h60
  text ".Print_Time" at 1826.72,-1473.07 h60
  text ".Print_Date" at 2555.72,-1473.07 h60
  text "GENERATED    :" at 3425.22,-1473.07 h60
  text "PLOT NAME =" at 5903.72,-1473.07 h40
  text ".plot_File_Name" at 5449,-1478.15 h40
M9 Title Sheet:
  drawing of 57 lines, arcs and shapes, not listed
  text "1" at 397.56,7628.26 h70
  text "2" at 2893.22,7628.26 h70
  text "3" at 5382.57,7628.26 h70
  text "4" at 7889.24,7628.26 h70
  text "5" at 10388.22,7628.26 h70
  text "6" at 12893.22,7628.26 h70
  text "A" at -758.78,6485.26 h70
  text "A" at 14041.22,6485.26 h70
  text "A" at 14043.25,6484.49 h70
  text "B" at -758.78,4105.26 h70
  text "B" at 14041.22,4105.26 h70
  text "B" at 14043.25,4104.49 h70
  text "C" at -758.78,1730.26 h70
  text "C" at 14041.22,1730.26 h70
  text "C" at 14043.25,1729.49 h70
  text "PROJECT TITLE:" at 11001.22,-130.74 h45
  text ".PRJ_Title" at 11051.22,-264.06 h70
  text "DESIGNED FOR:" at 11001.22,-431.74 h45
  text ".PRJ_Customer" at 11051.22,-571.74 h70
  text "D" at -758.78,-639.74 h70
  text "D" at 14041.22,-639.74 h70
  text "FILE NAME:" at 11001.22,-731.74 h45
  text ".PCB_File_Name_No_Path" at 11368.89,-853.09 h70
  text "Texas Instruments (TI) and/or its licensors do not warrant the accuracy or completeness of this specification" at 6031.72,-1013.57 h45
  text "ENGINEER:" at 11001.22,-1021.74 h45
  text "LAYOUT BY:" at 12506.22,-1021.74 h45
  text "or any information contained therein. TI and/or its licensors do not warrant that this design will meet" at 5986.74,-1126.24 h45
  text ".PRJ_Engineer" at 11051.22,-1176.73 h70
  text ".PCB_Layout" at 12556.72,-1176.73 h70
  text "the specifications, will be suitable for your application or fit for any particular purpose, or will operate in" at 5986.74,-1238.91 h45
  text "ALTIUM DESIGNER VERSION:" at 12506.22,-1331.74 h45
  text "an implementation. TI and/or its licensors do not warrant that the design is production worthy. You should" at 5986.74,-1351.57 h45
  text "completely validate and test your design implementation to confirm the system functionality for your application." at 6031.72,-1464.24 h45
  text ".print_Scale" at 11051.22,-1465.06 h70
  text ".Application_BuildNumber" at 12556.72,-1465.06 h70
  text "1" at 397.56,-1671.74 h70
  text "2" at 2893.22,-1671.74 h70
  text "3" at 5382.57,-1671.74 h70
  text "4" at 7889.24,-1671.74 h70
  text "5" at 10388.22,-1671.74 h70
  text "6" at 12893.22,-1671.74 h70
M10 Fab Notes:
  drawing of 227 lines, arcs and shapes, not listed
  text "DESIGN INFORMATION" at 12029.2,6391.71 h60
  text "(REFER ALSO ARRAY/PANEL PROFILING INFORMATION)" at 11677.68,6225.63 h60
  text "BOARD SIZE" at 10991.68,6221.35 h60
  text "65MM" at 11490.71,6109.99 h60
  text "160MM" at 12114.71,6102.99 h60
  text "X" at 11959.68,6093.52 h60
  text "Number of Layers :" at 11394.68,5896.35 h60
  text "4" at 12467.22,5891.35 h60
  text "10" at 12468.16,5759.55 h60
  text "MIN. TRACK WIDTH:" at 11394.68,5757.35 h60
  text "MIL" at 12645.68,5757.35 h60
  text "MIN. CLEARANCE:" at 11394.68,5625.35 h60
  text "6" at 12488.71,5625.99 h60
  text "MIL" at 12645.68,5625.35 h60
  text "12" at 12457,5501.85 h60
  text "MIN. VIA DRILL SIZE:" at 11394.68,5493.35 h60
  text "MIL" at 12645.68,5493.35 h60
  text "6 MIL ( 0.1524 mm)" at 12089.68,5351.64 h60
  text "MINIMUM ANNULAR RING" at 11065.45,5347.35 h60
  text "EXTERNAL" at 12981.22,5336.35 h60
  text "PER" at 11265.45,5229.35 h60
  text "IPC-D-275 CLASS 2 LEVEL C" at 11485.45,5229.35 h60
  text "+/-" at 12581.22,5116.35 h60
  text "MIL, HOLES" at 12973.68,5117.06 h60
  text "+/-" at 13435.22,5116.35 h60
  text "REGISTRATION TOLERANCES:" at 11065.45,5111.35 h60
  text "METAL" at 12265.22,5111.35 h60
  text "5" at 12841.43,5111.35 h60
  text "3" at 13674.43,5111.35 h60
  text "MIL" at 13790.68,5111.35 h60
  text "MATERIAL:" at 10990.68,4901.89 h60
  text "FR-4 High Tg" at 11977.13,4761.55 h60
  text "X" at 11818.22,4753.35 h60
  text "FR-408" at 11411.69,4752.98 h60
  text "OTHER" at 12899.68,4752.98 h60
  text "63 MIL (1.6mm) +/-10%" at 11731.79,4590.27 h60
  text "THICKNESS:" at 11065.45,4585.98 h60
  text "X" at 11603.62,4585.98 h60
  text "OTHER" at 13016.68,4585.98 h60
  text "TOLERANCE:" at 11065.45,4427.98 h60
  text "X" at 11904.76,4427.98 h60
  text "ANSI IPC-6012 TYPE 3 CLASS 2" at 12091.7,4427.98 h60
  text "OTHER +/-" at 12091.68,4271.98 h60
  text "BOW & TWIST:" at 11065.45,4114.98 h60
  text "X" at 11904.76,4114.98 h60
  text "ANSI IPC-6012 TYPE 3 CLASS 2" at 12091.7,4114.98 h60
  text "OTHER +/-" at 12091.68,3956.48 h60
  text "COPPER THICKNESS (FINISHED):" at 10990.68,3820.98 h60
  text "1.4MIL (1oz)" at 11870.68,3668.27 h60
  text "2MIL (1.4oz)" at 12637.68,3668.27 h60
  text "2.8MIL (2oz)" at 13364.68,3668.27 h60
  text "OUTER:" at 11347.68,3663.98 h60
  text "X" at 11742.22,3663.35 h60
  text "X" at 11738.22,3513.35 h60
  text "1.4MIL (1oz)" at 11870.68,3511.27 h60
  text "2.8MIL (2oz)" at 12637.68,3511.27 h60
  text "N/A" at 13364.22,3511.63 h60
  text "INNER SIGNAL:" at 11058.6,3506.98 h60
  text "DRILLING:" at 10990.68,3367.98 h60
  text "REFERENCE:" at 11065.45,3250.98 h60
  text "X" at 11713.68,3250.98 h60
  text "AS SHOWN" at 11900.68,3250.98 h60
  text "X" at 12614.68,3250.98 h60
  text "NC_DRILL FILES" at 12751.68,3250.98 h60
  text "PTH MIN COPPER THICKNESS:" at 11065.45,3092.98 h60
  text "X" at 12415.68,3092.98 h60
  text "1MIL" at 12552.68,3092.98 h60
  text "OTHER" at 13049.68,3092.98 h60
  text "BOARD FINISH:" at 10990.68,2933.98 h60
  text "SILKSCREEN:" at 11145.91,2815.98 h60
  text "X" at 12094.68,2815.98 h60
  text "TOP" at 12220.68,2815.98 h60
  text "BOTTOM" at 12731.68,2815.98 h60
  text "SILKSCREEN COLOR:" at 11145.91,2648.98 h60
  text "X" at 12093.64,2648.98 h60
  text "WHITE" at 12220.68,2648.98 h60
  text "OTHER" at 12731.68,2648.98 h60
  text "SOLDER RESIST COLOR:" at 11145.91,2478.98 h60
  text "X" at 11713.65,2319.79 h60
  text "GREEN" at 11840.68,2319.79 h60
  text "BLUE" at 12431.68,2319.79 h60
  text "OTHER" at 12969.68,2319.79 h60
  text "IMMERSION GOLD (ENIG)" at 12051.68,2131.27 h60
  text "ENEPIG" at 13389.22,2127.98 h60
  text "SURFACE FINISH:" at 10990.68,2126.98 h60
  text "X" at 11864.74,2126.98 h60
  text "IMM. TIN/SILVER OR EQUIV" at 11320.22,1969.98 h60
  text "OTHER" at 12751.68,1969.98 h60
  text "X" at 11860.68,1795.98 h60
  text "ARRAY/PANEL:" at 10990.68,1790.98 h60
  text "CUT AND TRIM PER MECH LAYER 1" at 12051.68,1786.7 h60
  text "N.C. ROUTE" at 12051.68,1634.98 h60
  text "V. SCORE" at 12917.68,1634.98 h60
  text "CERTIFICATION:" at 10990.68,1497.98 h60
  text "MATERIALS AND WORKMANSHIP FOR ALL PCBS" at 11715.68,1497.98 h60
  text "TO MEET OR EXCEED THE REQUIREMENTS OF:" at 11715.68,1399.98 h60
  text "X" at 11342.19,1263.48 h60
  text "ANSI IPC-A-600F CLASS ->" at 11481.19,1263.48 h60
  text "X" at 13120.24,1263.48 h60
  text "2" at 13239.19,1263.48 h60
  text "1" at 12924.19,1261.98 h60
  text "3" at 13593.19,1261.98 h60
  text "X" at 11344.24,1103.98 h60
  text "UL 94V-0" at 11481.19,1103.98 h60
  text "X" at 12156.24,1103.98 h60
  text "RoHS" at 12293.19,1103.98 h60
  text "OTHER" at 12937.59,1103.98 h60
  text "PER ORDER" at 13334.65,1103.98 h60
  text "VIA TENTING:" at 12208.22,970.35 h60
  text "X" at 13290,966.85 h60
  text "ADDITIONAL REQUIREMENTS:" at 10990.68,962.98 h60
  text "YES" at 12757.89,961.26 h60
  text "NO" at 13122.7,956.04 h60
  text "MICROSECTION:" at 11065.45,847.98 h60
  text "YES" at 11971.19,847.98 h60
  text "IMPEDANCE CONTROL:" at 12230.22,841.35 h60
  text "YES" at 13214.22,840.35 h60
  text "X" at 13756.22,833.35 h60
  text "NO" at 13589.7,823.04 h60
  text "REQUIRED" at 12832.68,691.84 h60
  text "BARE BOARD ELEC. TEST:" at 11065.45,688.98 h60
  text "NONE" at 12371.19,688.98 h60
  text "X" at 12705.68,688.98 h60
  text "PER ORDER" at 13424.68,688.98 h60
  text "MANUFACTURER'S UL:" at 11065.45,531.98 h60
  text "RAIL" at 12231.19,527.7 h60
  text "METAL" at 12723,527.7 h60
  text "X" at 13098.22,527.35 h60
  text "SILK" at 13234.68,527.7 h60
M11 Gerber Information:
  lines w10: -634.28,-1338.4 5965.72,-1338.4 ; -634.28,-1135.07 5967.72,-1135.07 ; -634.28,-931.74 -634.28,-1541.74 3370.72,-1541.74 5967.72,-1541.74 5967.72,-931.74 -633.78,-931.74 -633.78,-1541.74 941.72,-1541.74 ; 1873.72,-1541.74 1873.72,-931.74 ; 3426.72,-1135.07 3426.72,-931.74 ; 3937.72,-1135.07 3937.72,-931.74 ; 4559.72,-1548.24 4559.72,-1345.4
  text "ALL ARTWORK VIEWED FROM TOP SIDE" at -570.78,-1063.9 h60
  text "BOARD #:" at 1905.72,-1063.9 h60
  text "SVN REV:" at 4133.72,-1063.9 h60
  text ".VersionControl_RevNumber" at 4639.72,-1063.9 h60
  text ".PRJ_Number" at 2353,-1065.15 h40
  text "REV:" at 3564,-1078.15 h60
  text ".PCB_Rev" at 3817,-1078.15 h60
  text "LAYER NAME =" at -570.78,-1266.73 h60
  text "TID #:" at 1905.72,-1267.24 h60
  text ".TID" at 2451.22,-1267.24 h60
  text ".plot_File_Name" at 78,-1463.15 h40
  text "PLOT NAME =" at -570.78,-1472.57 h60
  text "GENERATED    :" at 1907.72,-1472.57 h60
  text ".Print_Date" at 2777.22,-1472.57 h60
  text ".Print_Time" at 3506.22,-1472.57 h60
  text "TEXAS INSTRUMENTS" at 4770.72,-1472.57 h60
M12 Stackup:
  drawing of 295 lines, arcs and shapes, not listed
  text "Layer" at 4145.84,6399.85 h60
  text "Name" at 4555.75,6399.85 h60
  text "Material" at 5485.5,6399.85 h60
  text "Thickness" at 6345.26,6399.85 h60
  text "Constant" at 6995.1,6399.85 h60
  text "Board Layer Stack" at 7564.96,6399.85 h60
  text "1" at 4145.84,6279.85 h60
  text "Top Overlay" at 4555.75,6279.85 h60
  text "2" at 4145.84,6159.85 h60
  text "Top Solder" at 4555.75,6159.85 h60
  text "Solder Resist" at 5485.5,6159.85 h60
  text "0.40mil" at 6345.26,6159.85 h60
  text "3.5" at 6995.1,6159.85 h60
  text "3" at 4145.84,6039.85 h60
  text "Top Layer" at 4555.75,6039.85 h60
  text "Copper" at 5485.5,6039.85 h60
  text "1.40mil" at 6345.26,6039.85 h60
  text "4" at 4145.84,5919.85 h60
  text "Dielectric 1" at 4555.75,5919.85 h60
  text "FR-4 High Tg" at 5485.5,5919.85 h60
  text "8.00mil" at 6345.26,5919.85 h60
  text "4.2" at 6995.1,5919.85 h60
  text "5" at 4145.84,5799.85 h60
  text "GND Layer" at 4555.75,5799.85 h60
  text "Copper" at 5485.5,5799.85 h60
  text "1.40mil" at 6345.26,5799.85 h60
  text "6" at 4145.84,5679.85 h60
  text "Dielectric 2" at 4555.75,5679.85 h60
  text "FR-4 High Tg" at 5485.5,5679.85 h60
  text "40.00mil" at 6345.26,5679.85 h60
  text "4.2" at 6995.1,5679.85 h60
  text "7" at 4145.84,5559.85 h60
  text "PWR Layer" at 4555.75,5559.85 h60
  text "Copper" at 5485.5,5559.85 h60
  text "1.40mil" at 6345.26,5559.85 h60
  text "8" at 4145.84,5439.85 h60
  text "Dielectric 3" at 4555.75,5439.85 h60
  text "FR-4 High Tg" at 5485.5,5439.85 h60
  text "8.00mil" at 6345.26,5439.85 h60
  text "4.2" at 6995.1,5439.85 h60
  text "9" at 4145.84,5319.85 h60
  text "Bottom Layer" at 4555.75,5319.85 h60
  text "Copper" at 5485.5,5319.85 h60
  text "1.40mil" at 6345.26,5319.85 h60
  text "10" at 4145.84,5199.85 h60
  text "Bottom Solder" at 4555.75,5199.85 h60
  text "Solder Resist" at 5485.5,5199.85 h60
  text "0.40mil" at 6345.26,5199.85 h60
  text "3.5" at 6995.1,5199.85 h60
  text "11" at 4145.84,5079.85 h60
  text "Bottom Overlay" at 4555.75,5079.85 h60
M13 Component Bodies Top:
  text ".Layer_Name" at 234.72,-1266.73 h60
M14 Component Bodies Bottom:
  text ".Layer_Name" at 234.72,-1266.73 h60
M15 Courtyards Top:
  text ".Layer_Name" at 234.72,-1266.73 h60
M16 Courtyards Bottom:
  text ".Layer_Name" at 234.72,-1266.73 h60
Drill Drawing:
  circle w10: c3671.63,2279.13 r33.33
  lines w10: 3638.29,1862.46 3704.96,1862.46 3671.63,1795.79 3638.29,1862.46 ; 3638.29,1945.79 3704.96,1945.79 3704.96,2012.46 3638.29,2012.46 3638.29,1945.79 ; 3638.29,2112.46 3654.96,2112.46 3671.63,2095.79 3688.29,2112.46 3704.96,2112.46 3688.29,2129.13 3704.96,2145.79 3688.29,2145.79 3671.63,2162.46 3654.96,2145.79 3638.29,2145.79 3654.96,2129.13 3638.29,2112.46 ; 3638.29,2395.79 3638.29,2412.46 3654.96,2429.13 3638.29,2445.79 3638.29,2462.46 3654.96,2462.46 3671.63,2445.79 3688.29,2462.46 3704.96,2462.46 3704.96,2445.79 3688.29,2429.13 3704.96,2412.46 3704.96,2395.79 3688.29,2395.79 3671.63,2412.46 3654.96,2395.79 3638.29,2395.79 ; 3638.29,2562.46 3654.96,2562.46 3654.96,2545.79 3688.29,2545.79 3688.29,2562.46 3704.96,2562.46 3704.96,2595.79 3688.29,2595.79 3688.29,2612.46 3654.96,2612.46 3654.96,2595.79 3638.29,2595.79 3638.29,2562.46 ; 3638.29,2695.79 3671.63,2712.46 3704.96,2695.79 3688.29,2729.13 3704.96,2762.46 3671.63,2745.79 3638.29,2762.46 3654.96,2729.13 3638.29,2695.79
  lines w15: 3578.5,1750.79 7113.57,1750.79 ; 3578.5,2800.79 7113.57,2800.79 ; 4129.38,1600.79 4129.38,2950.79 ; 4729.22,1600.79 4729.22,2950.79 ; 5828.9,1600.79 5828.9,2950.79 ; 6334.77,1600.79 6334.77,2950.79 ; 3578.5,1600.79 7113.57,1600.79 7113.57,2950.79 3578.5,2950.79 3578.5,1600.79
  text "Symbol" at 3668.5,2845.79 h72
  text "Count" at 4174.38,2845.79 h72
  text "Hole Size" at 4774.22,2845.79 h72
  text "Plated" at 5873.9,2845.79 h72
  text "Hole Type" at 6379.77,2845.79 h72
  text "4" at 4174.38,2695.79 h60
  text "0.200mm (7.87mil)" at 4774.22,2695.79 h60
  text "PTH" at 5873.9,2695.79 h60
  text "Round" at 6379.77,2695.79 h60
  text "8" at 4174.38,2545.79 h60
  text "0.813mm (32.00mil)" at 4774.22,2545.79 h60
  text "NPTH" at 5873.9,2545.79 h60
  text "Slot" at 6379.77,2545.79 h60
  text "10" at 4174.38,2395.79 h60
  text "0.406mm (16.00mil)" at 4774.22,2395.79 h60
  text "PTH" at 5873.9,2395.79 h60
  text "Round" at 6379.77,2395.79 h60
  text "14" at 4174.38,2245.79 h60
  text "1.250mm (49.21mil)" at 4774.22,2245.79 h60
  text "PTH" at 5873.9,2245.79 h60
  text "Round" at 6379.77,2245.79 h60
  text "17" at 4174.38,2095.79 h60
  text "0.900mm (35.43mil)" at 4774.22,2095.79 h60
  text "PTH" at 5873.9,2095.79 h60
  text "Round" at 6379.77,2095.79 h60
  text "40" at 4174.38,1945.79 h60
  text "1.016mm (40.00mil)" at 4774.22,1945.79 h60
  text "PTH" at 5873.9,1945.79 h60
  text "Round" at 6379.77,1945.79 h60
  text "230" at 4174.38,1795.79 h60
  text "0.305mm (12.00mil)" at 4774.22,1795.79 h60
  text "PTH" at 5873.9,1795.79 h60
  text "Round" at 6379.77,1795.79 h60
  text "323 Total" at 4174.38,1645.79 h60
  text "Slot definitions :" at 3668.5,1500.82 h60
  text "Routed Path Length" at 4701.19,1500.82 h60
  text "= Calculated from tool start centre position to tool end centre position." at 5803.86,1500.82 h60
  text "Hole Length" at 4701.19,1400.84 h60
  text "= Routed Path Length + Tool Size = Slot length as defined in the PCB layout" at 5393.99,1400.84 h60
  text "Drill Table" at 3568,1178.07 h60
  text "FOR 12MIL DRILL +0/-12MIL" at 3566,1080.52 h60
  text "FOR 16MIL DRILL +0/-16MIL" at 3566,984.96 h60
  text "FOR PTH DRILL +/-3MIL" at 3566,889.41 h60
  text "FOR NPTH DRILL +/-2MIL" at 3566,793.85 h60
  text ".Layer_Name" at 234.72,-1266.73 h60
Mechanical 17:
  text ".Layer_Name" at 234.72,-1266.73 h60
Mechanical 18:
  text ".Layer_Name" at 234.72,-1266.73 h60
Mechanical 19:
  text ".Layer_Name" at 234.72,-1266.73 h60

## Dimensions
0,0 to 0,6299.21 on M2 Board Dimensions
0,0 to 2559.06,0 on M2 Board Dimensions
-342.28,-808.24 to 657.72,-808.24 on M2 Board Dimensions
